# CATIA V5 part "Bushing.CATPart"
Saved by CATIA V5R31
Part number: Bushing
Bounding box of the stored display mesh (mm): x -13.45 to 13.45, y 0 to 63, z -13.45 to 13.45
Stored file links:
  D:\PROJECTS\Project 2021\US EDITION\CATIA V5 6R 2021\Resources\Part Files\c14_catia_v5_6r2021_prt\c14-catia-v5-6r2021-figr-14-26 & 27\Part & Asm\Bushing.CATPart
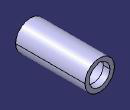
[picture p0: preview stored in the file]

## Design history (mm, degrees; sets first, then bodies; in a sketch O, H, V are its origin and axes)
Body1 (main body)
  Sketch1 on zx-plane, origin (0, 0, 0), H (-1, 0, 0), V (0, 0, 1)
    circle A1 centre (0, 0) radius 9.5
    circle A2 centre (0, 0) radius 13.45
    radius A1 = 9.5
    radius A2 = 13.45
  Pad1: profile Sketch1, direction (0, 1, 0), length 63
  Sketch2 on face of Pad1, origin (0, 63, 0), H (-1, 0, 0), V (0, 0, 1)
    line L1 (-1.5, 9.3808) -> (1.5, 9.3808)
    line L2 (1.5, 9.3808) -> (1.5, 10.1808)
    line L3 (1.5, 10.1808) -> (-1.5, 10.1808)
    line L4 (-1.5, 10.1808) -> (-1.5, 9.3808)
    point P2 (1.5, 9.3808)
    reference projected circle E1 centre (0, 0) radius 9.5 from edge of Pad1
    length L3 = 3
    length L2 = 0.8
    distance V L4 = 1.5
    horizontal: L1 H, L3 H
    vertical: L2 V, L4 V
    coincidence: P2 E1
  Pocket1: profile Sketch2, direction (0, -1, 0), through (limit type 6)
  Sketch3 on xy-plane, origin (0, 0, 0), H (1, 0, 0), V (0, 1, 0)
    line L1 (9.5, 57) -> (10.3, 57)
    line L2 (10.3, 57) -> (10.3, 49)
    line L3 (10.3, 49) -> (9.5, 49)
    line L4 (9.5, 49) -> (9.5, 57)
    reference projected line E1 (13.45, 63) -> (-13.45, 63) from edge of Pad1
    length L2 = 8
    length L1 = 0.8
    distance L3 E1 = 14
    distance V L4 = 9.5
    horizontal: L1 H, L3 H
    vertical: L2 V, L4 V
  Groove1: profile Sketch3, axis axis of face of Pad1, angle 360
